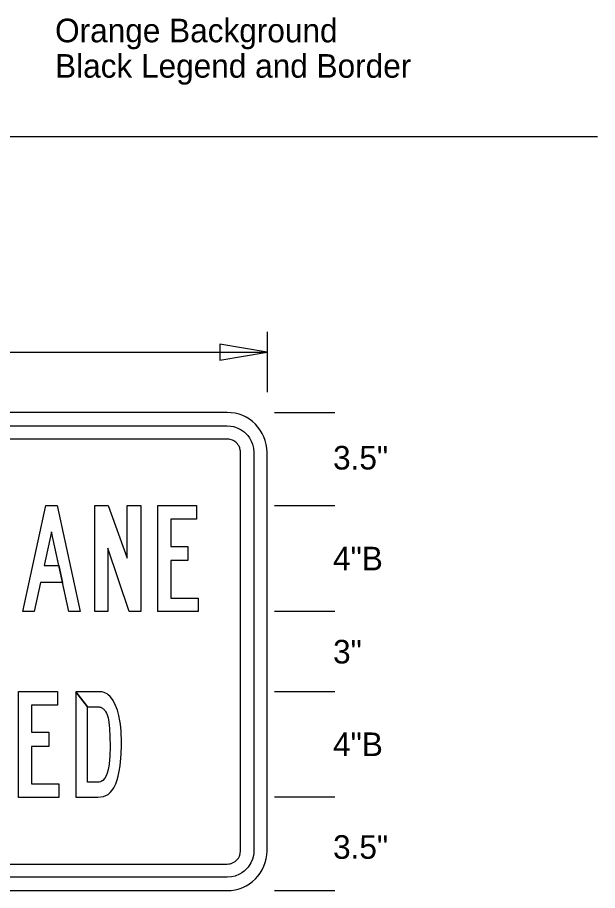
# Model space of a CAD drawing. Extents: x 0 to 770, y 0 to 495.
# Drawn here: x 684 to 770, y 218.2 to 347.6 of the extents above; entities that cross this region are included whole.
import ezdxf

# ---------------------------------------------------------------- set-up
doc = ezdxf.new("R2010")
doc.units = 0
for name, color, linetype in [('Default', 7, 'Continuous'), ('Dimension', 7, 'Continuous'), ('GSBWFill', 7, 'Continuous'), ('GSColorFill', 7, 'Continuous'), ('GSDims', 7, 'Continuous'), ('GSOutline', 7, 'Continuous'), ('SheetLines_dp', 7, 'Continuous'), ('TextStructures', 7, 'Continuous')]:
    doc.layers.add(name, color=color, linetype=linetype)

msp = doc.modelspace()

# ---------------------------------------------------------------- linework, layer by layer
at = {"layer": 'Default'}
for p, q in [((715.09, 289.06), (632.41, 289.06)), ((720.99, 224.1), (720.99, 283.16)), ((632.41, 218.2), (715.09, 218.2))]:
    msp.add_line(p, q, dxfattribs=at)
for points in [[(632.41, 287.09), (715.09, 287.09), (715.64, 287.06), (716.02, 286.98), (716.32, 286.9), (716.78, 286.71), (717.17, 286.5), (717.58, 286.21), (717.87, 285.94), (718.15, 285.64), (718.39, 285.3), (718.66, 284.81), (718.83, 284.37), (718.98, 283.78), (719.03, 283.16), (719.03, 282.46), (719.03, 281.42), (719.03, 224.1), (719.01, 223.76), (718.96, 223.41), (718.82, 222.85), (718.6, 222.32), (718.18, 221.66), (717.87, 221.32), (717.62, 221.09), (717.25, 220.81), (717.25, 220.81), (716.9, 220.61), (716.9, 220.61), (716.25, 220.34), (716.25, 220.34), (715.71, 220.21), (715.09, 220.17), (632.41, 220.17)], [(632.65, 222.13), (715.09, 222.13), (715.33, 222.15), (715.52, 222.18), (715.67, 222.22), (715.87, 222.3), (715.99, 222.35), (715.99, 222.35), (716.25, 222.52), (716.48, 222.71), (716.48, 222.71), (716.66, 222.92), (716.74, 223.02), (716.74, 223.02), (716.89, 223.3), (716.95, 223.46), (716.95, 223.46), (717.02, 223.7), (717.02, 223.7), (717.06, 224.1), (717.06, 283.16), (717.05, 283.34), (717.02, 283.51), (716.94, 283.82), (716.84, 284.06), (716.73, 284.25), (716.6, 284.42), (716.34, 284.67), (716.2, 284.78), (716.07, 284.87), (715.86, 284.97), (715.86, 284.97), (715.52, 285.08), (715.34, 285.11), (715.09, 285.13), (632.41, 285.13)]]:
    msp.add_lwpolyline(points, dxfattribs=at)
for points in [[(695.48, 275.29), (697.43, 275.29), (700.25, 267.5), (700.25, 275.29), (702.27, 275.29), (702.27, 259.55), (700.54, 259.55), (697.4, 268.95), (697.4, 259.55), (695.48, 259.55)], [(704.79, 275.29), (710.55, 275.29), (710.55, 273.25), (706.72, 273.25), (706.72, 269.21), (709.27, 269.21), (709.27, 267.12), (706.72, 267.12), (706.72, 261.56), (710.77, 261.56), (710.77, 259.55), (704.79, 259.55)], [(684.14, 247.73), (689.9, 247.73), (689.9, 245.69), (686.08, 245.69), (686.08, 241.66), (688.63, 241.66), (688.63, 239.56), (686.08, 239.56), (686.08, 234), (690.12, 234), (690.12, 231.99), (684.14, 231.99)], [(692.64, 232.05), (695.92, 232.05), (696.73, 232.13), (697.42, 232.43), (697.75, 232.73), (698.05, 233.1), (698.25, 233.4), (698.56, 234.04), (698.77, 234.62), (698.92, 235.16), (699.08, 235.91), (699.2, 236.67), (699.28, 237.35), (699.32, 237.78), (699.37, 238.53), (699.41, 239.67), (699.41, 240.55), (699.38, 241.49), (699.36, 241.85), (699.26, 242.88), (699.18, 243.37), (699.02, 244.14), (698.81, 244.93), (698.54, 245.65), (698.19, 246.35), (697.94, 246.71), (697.72, 246.97), (697.43, 247.23), (697.26, 247.35), (697.02, 247.48), (696.86, 247.55), (696.68, 247.6), (696.47, 247.65), (696.32, 247.66), (692.64, 247.67), (694.37, 245.44), (694.73, 245.44), (695.12, 245.44), (695.86, 245.44), (695.94, 245.43), (695.98, 245.43), (696.11, 245.42), (696.21, 245.4), (696.33, 245.36), (696.4, 245.33), (696.51, 245.28), (696.6, 245.22), (696.68, 245.16), (696.77, 245.09), (696.86, 244.99), (697, 244.82), (697.06, 244.72), (697.17, 244.5), (697.27, 244.26), (697.33, 244.1), (697.41, 243.79), (697.47, 243.52), (697.53, 243.14), (697.58, 242.71), (697.62, 242.22), (697.65, 241.82), (697.67, 241.42), (697.69, 240.94), (697.7, 240.71), (697.72, 239.92), (697.72, 239.63), (697.71, 239.07), (697.7, 238.55), (697.68, 238.07), (697.65, 237.63), (697.58, 236.87), (697.5, 236.41), (697.45, 236.14), (697.29, 235.58), (697.12, 235.19), (696.93, 234.86), (696.63, 234.53), (696.41, 234.38), (696.3, 234.33), (696.12, 234.27), (695.81, 234.24), (694.37, 234.24), (694.37, 245.44), (692.64, 247.67)]]:
    msp.add_lwpolyline(points, close=True, dxfattribs=at)
for centre, start, end in [((715.09, 283.16), 0, 90), ((715.09, 224.1), 270, 0)]:
    msp.add_arc(centre, 5.91, start, end, dxfattribs=at)
at = {"layer": 'Dimension'}
msp.add_lwpolyline([(720.99, 298.01), (713.98, 299.2), (713.98, 296.82)], close=True, dxfattribs=at)
at = {"layer": 'GSBWFill'}
msp.add_lwpolyline([(684.77, 259.55), (688.17, 275.29), (689.87, 275.29), (693.27, 259.55), (691.58, 259.55), (689.02, 271.4), (687.94, 266.39), (690.1, 266.39), (690.65, 263.87), (687.4, 263.87), (686.46, 259.55)], close=True, dxfattribs=at)
at = {"layer": 'GSColorFill'}
msp.add_lwpolyline([(684.77, 259.55), (688.17, 275.29), (689.87, 275.29), (693.27, 259.55), (691.58, 259.55), (689.02, 271.4), (687.94, 266.39), (690.1, 266.39), (690.65, 263.87), (687.4, 263.87), (686.46, 259.55)], close=True, dxfattribs=at)
at = {"layer": 'GSDims'}
for p, q in [((720.99, 301.03), (720.99, 292.08)), ((626.51, 298.01), (720.99, 298.01)), ((722.09, 289.06), (731.04, 289.06)), ((722.09, 275.29), (731.04, 275.29)), ((731.04, 259.55), (722.09, 259.55)), ((731.04, 247.67), (722.09, 247.67)), ((722.09, 232.09), (731.04, 232.09)), ((722.09, 218.2), (731.04, 218.2))]:
    msp.add_line(p, q, dxfattribs=at)
at = {"layer": 'GSOutline'}
for points in [[(687.4, 263.87), (686.46, 259.55), (684.77, 259.55), (688.17, 275.29), (689.87, 275.29), (693.27, 259.55), (691.58, 259.55), (690.65, 263.87)], [(687.94, 266.39), (690.1, 266.39), (689.02, 271.4)]]:
    msp.add_lwpolyline(points, close=True, dxfattribs=at)
at = {"layer": 'SheetLines_dp'}
msp.add_line((0, 330), (770, 330), dxfattribs=at)

# ---------------------------------------------------------------- texts
at = {"layer": 'TextStructures'}
for s, p in [('Orange Background', (689.56, 343.96)), ('Black Legend and Border  ', (689.56, 338.71)), ('3.5"', (730.78, 280.62)), ('4"B', (730.78, 265.67)), ('3"', (730.78, 251.86)), ('4"B', (730.78, 238.13)), ('3.5"', (730.78, 222.9))]:
    msp.add_text(s, height=3.5, dxfattribs=at).set_placement(p)

doc.saveas('drawing.dxf')
